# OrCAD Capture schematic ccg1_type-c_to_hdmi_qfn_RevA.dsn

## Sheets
1 PAGE03 : Type-C/Power: size B; title: CCG1 40-QFN Type-C To HDMI Reference Schematic; rev: A
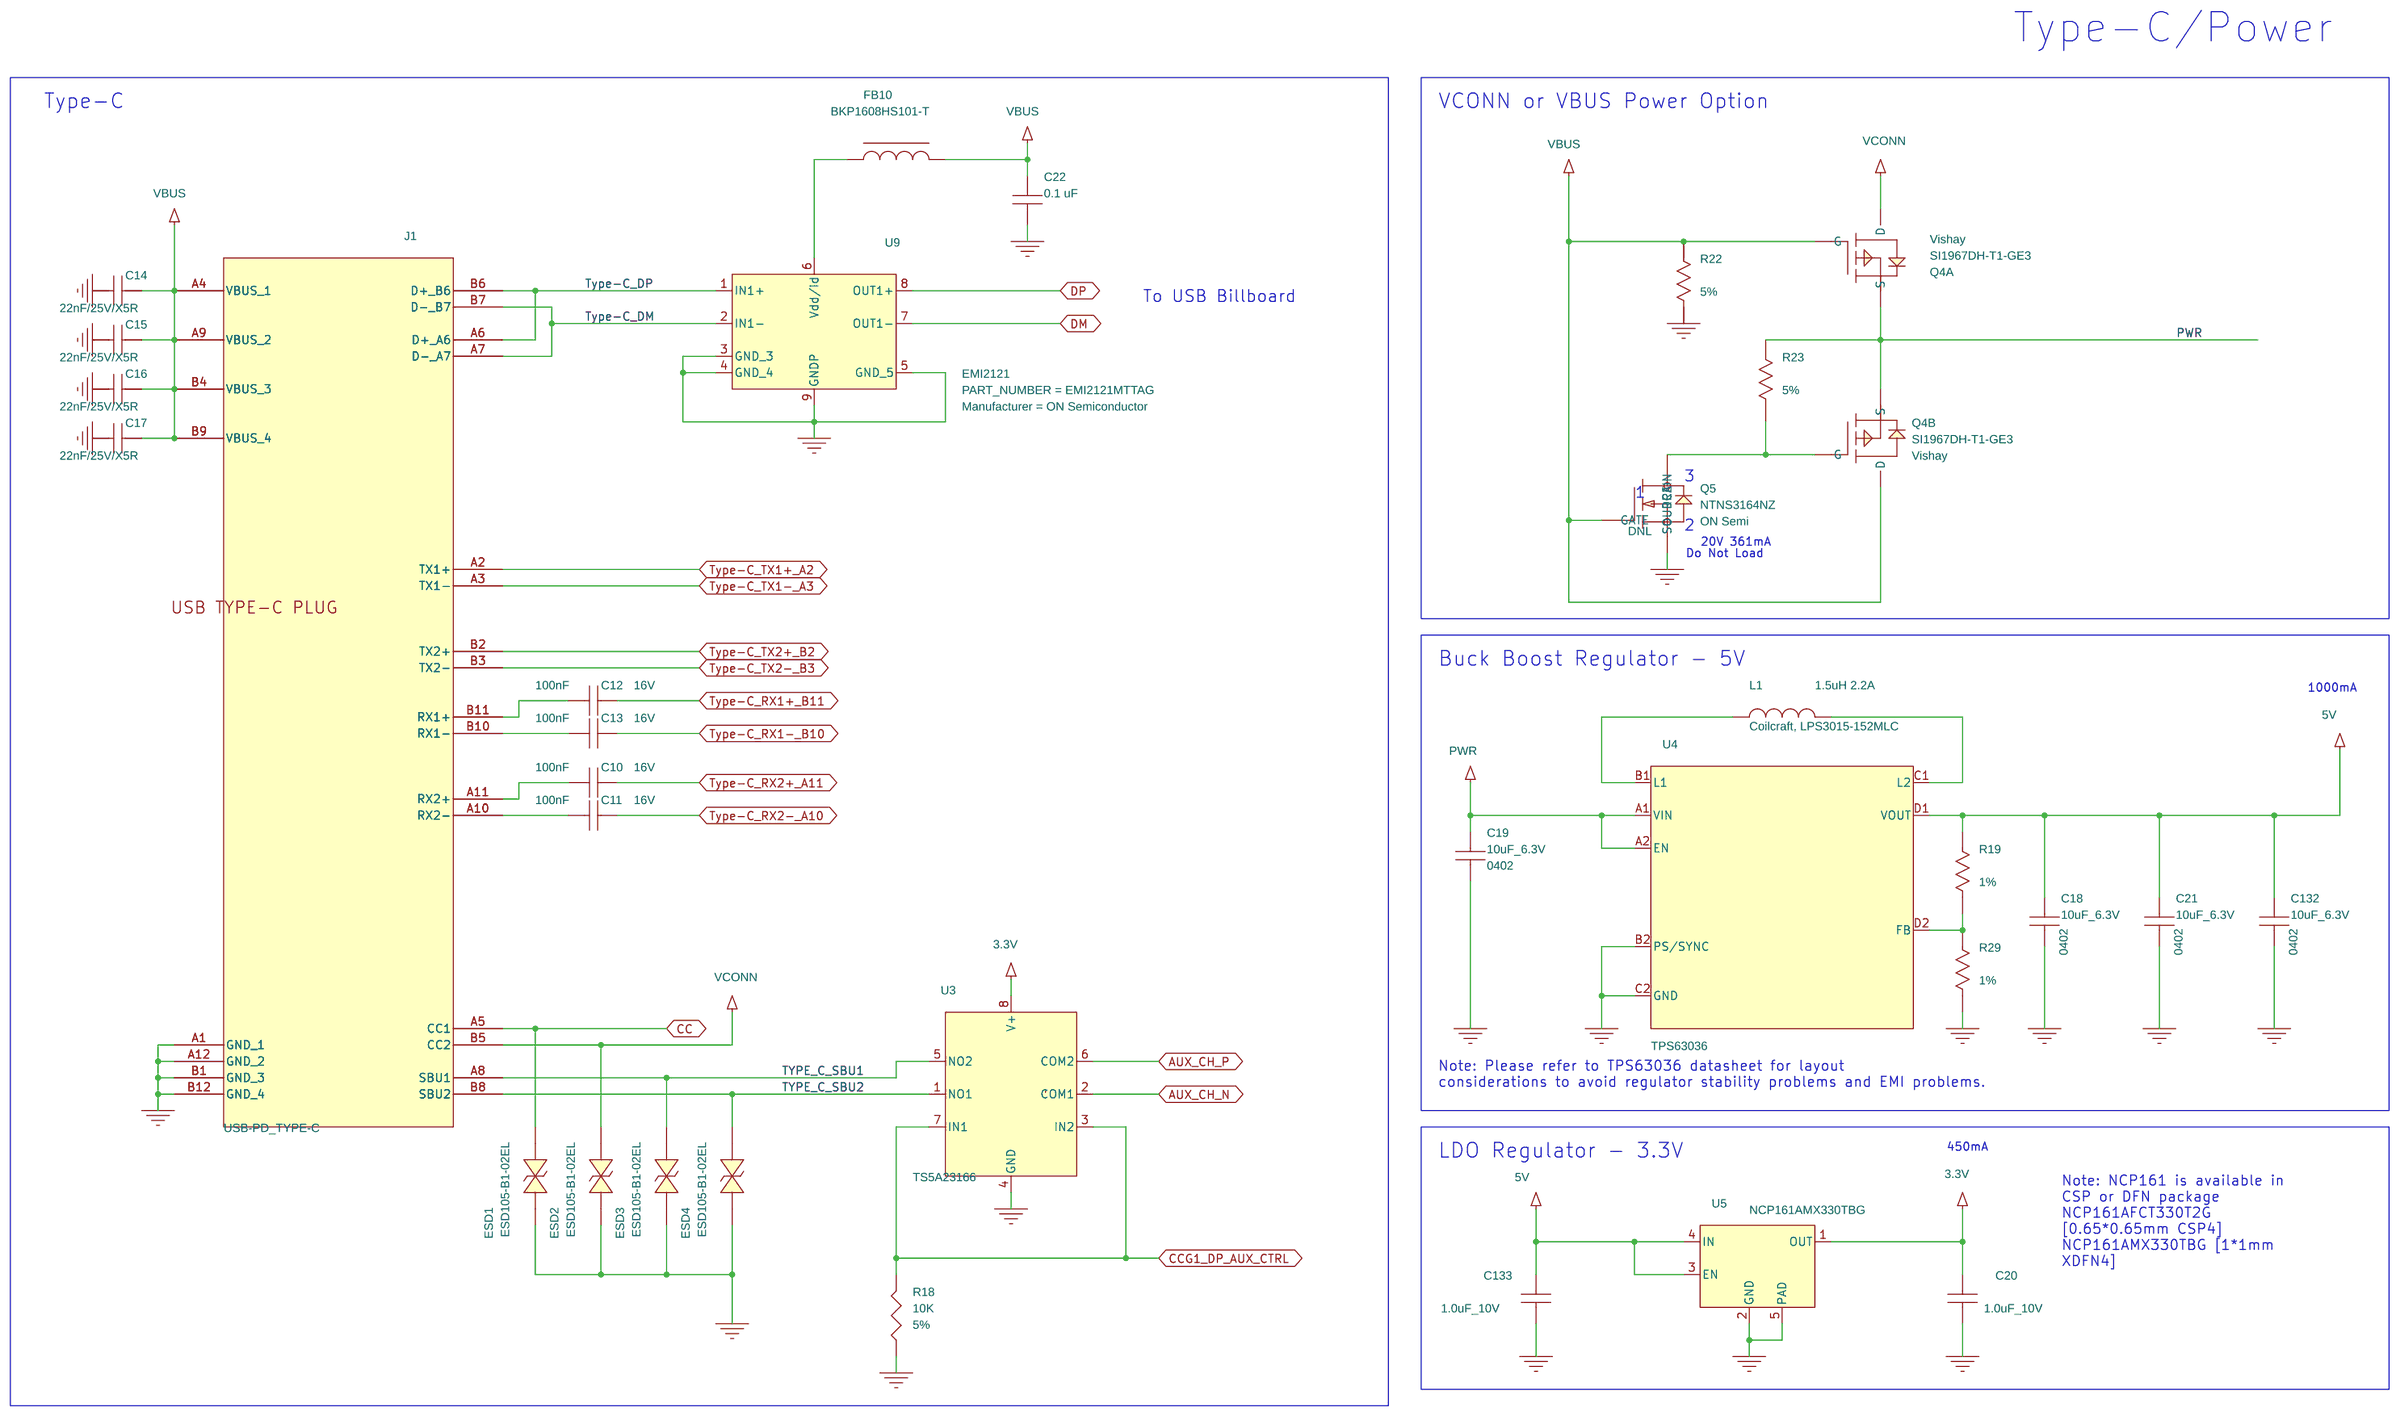
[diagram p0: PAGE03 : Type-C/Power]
2 PAGE01 : Title
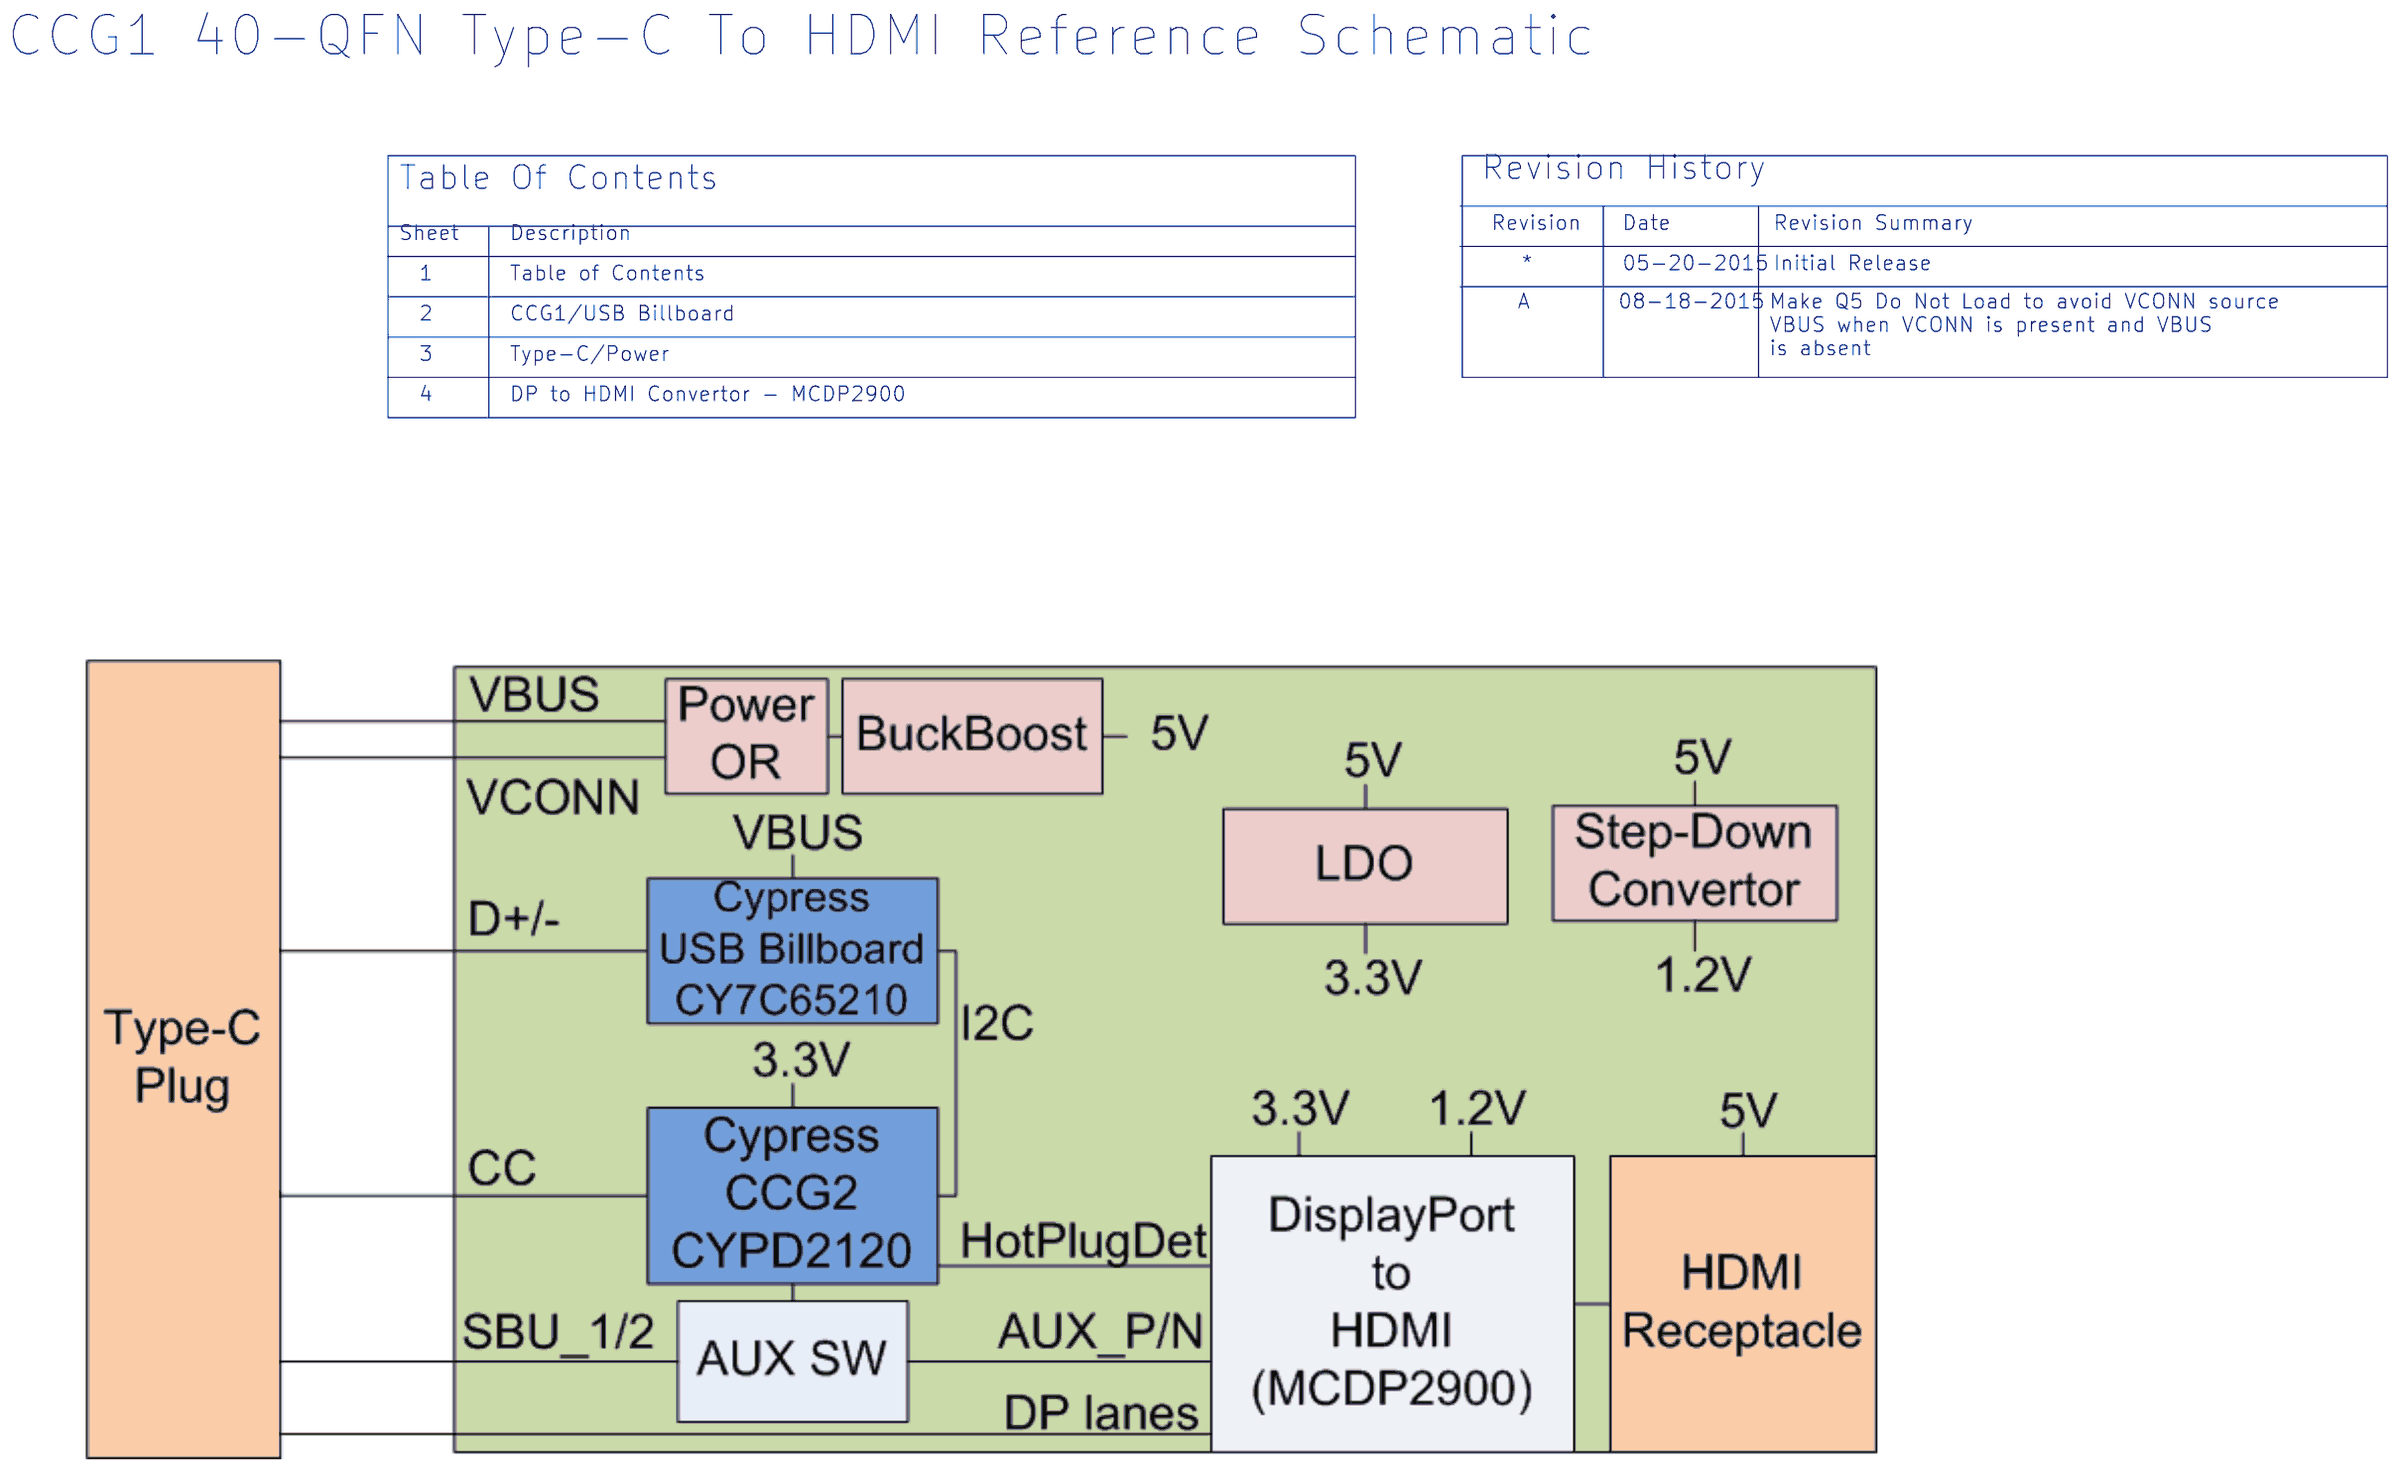
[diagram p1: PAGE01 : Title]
3 PAGE02 : CCG1/USB Billboard: size B
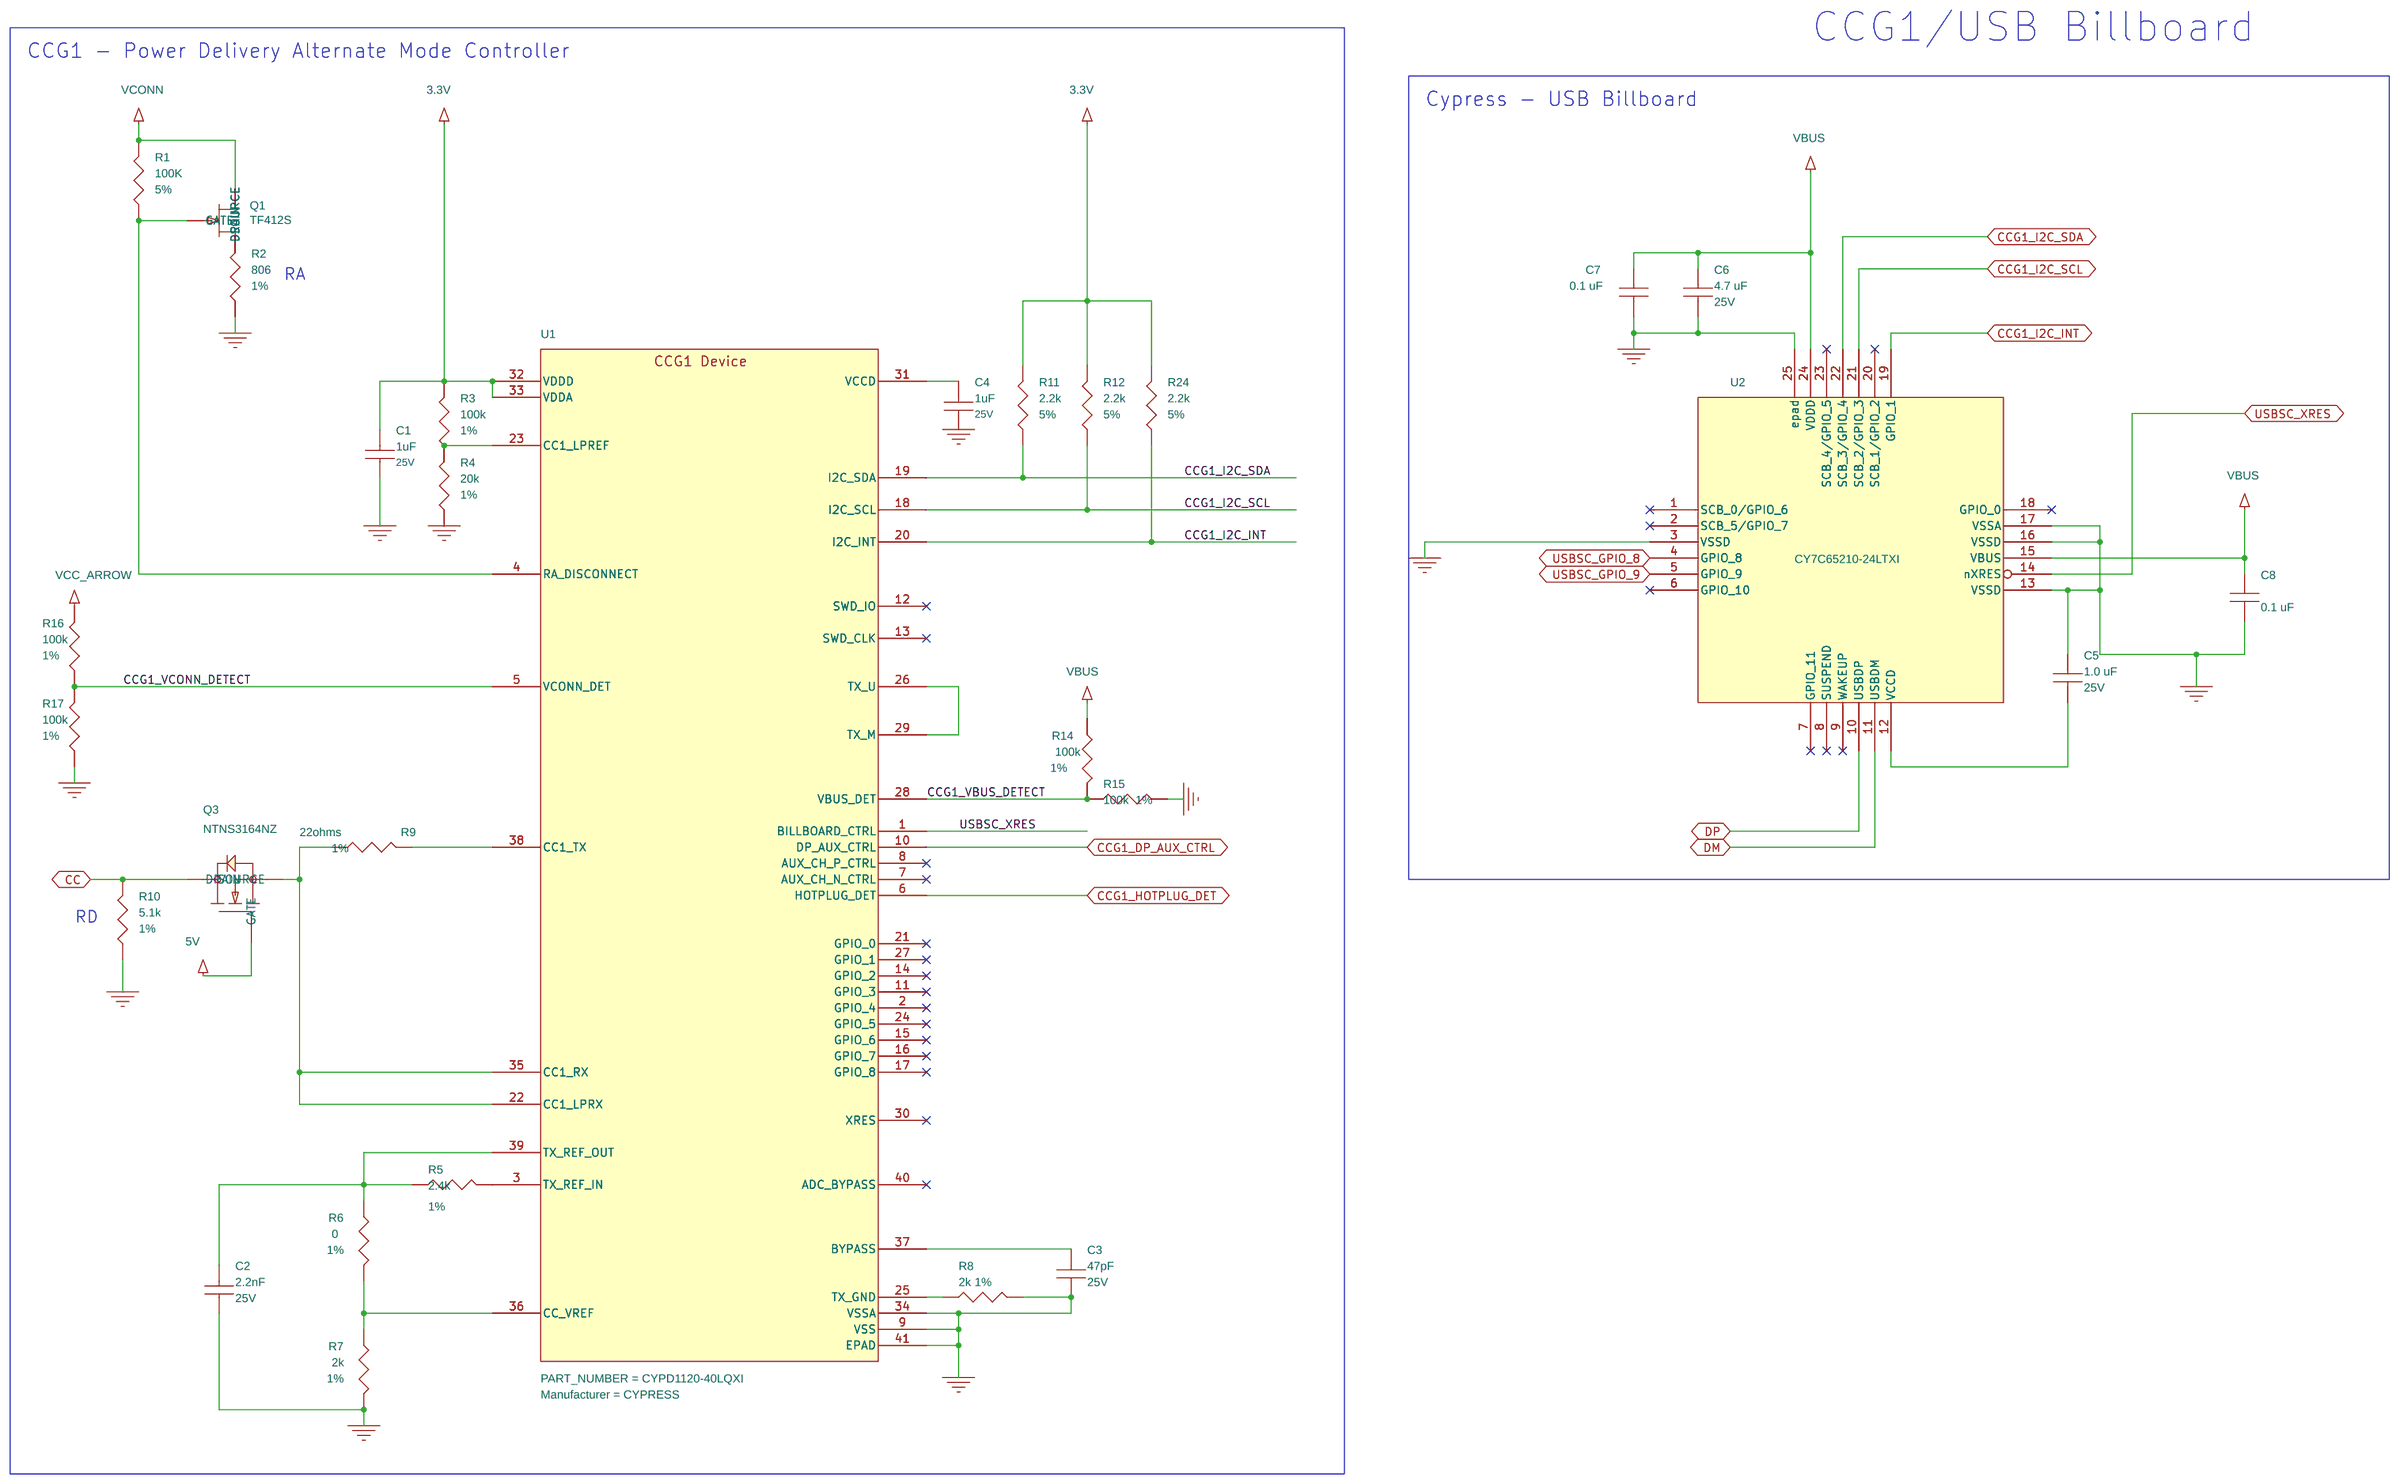
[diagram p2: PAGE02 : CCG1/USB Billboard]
4 PAGE04 : DP to HDMI MCDP2900: size C
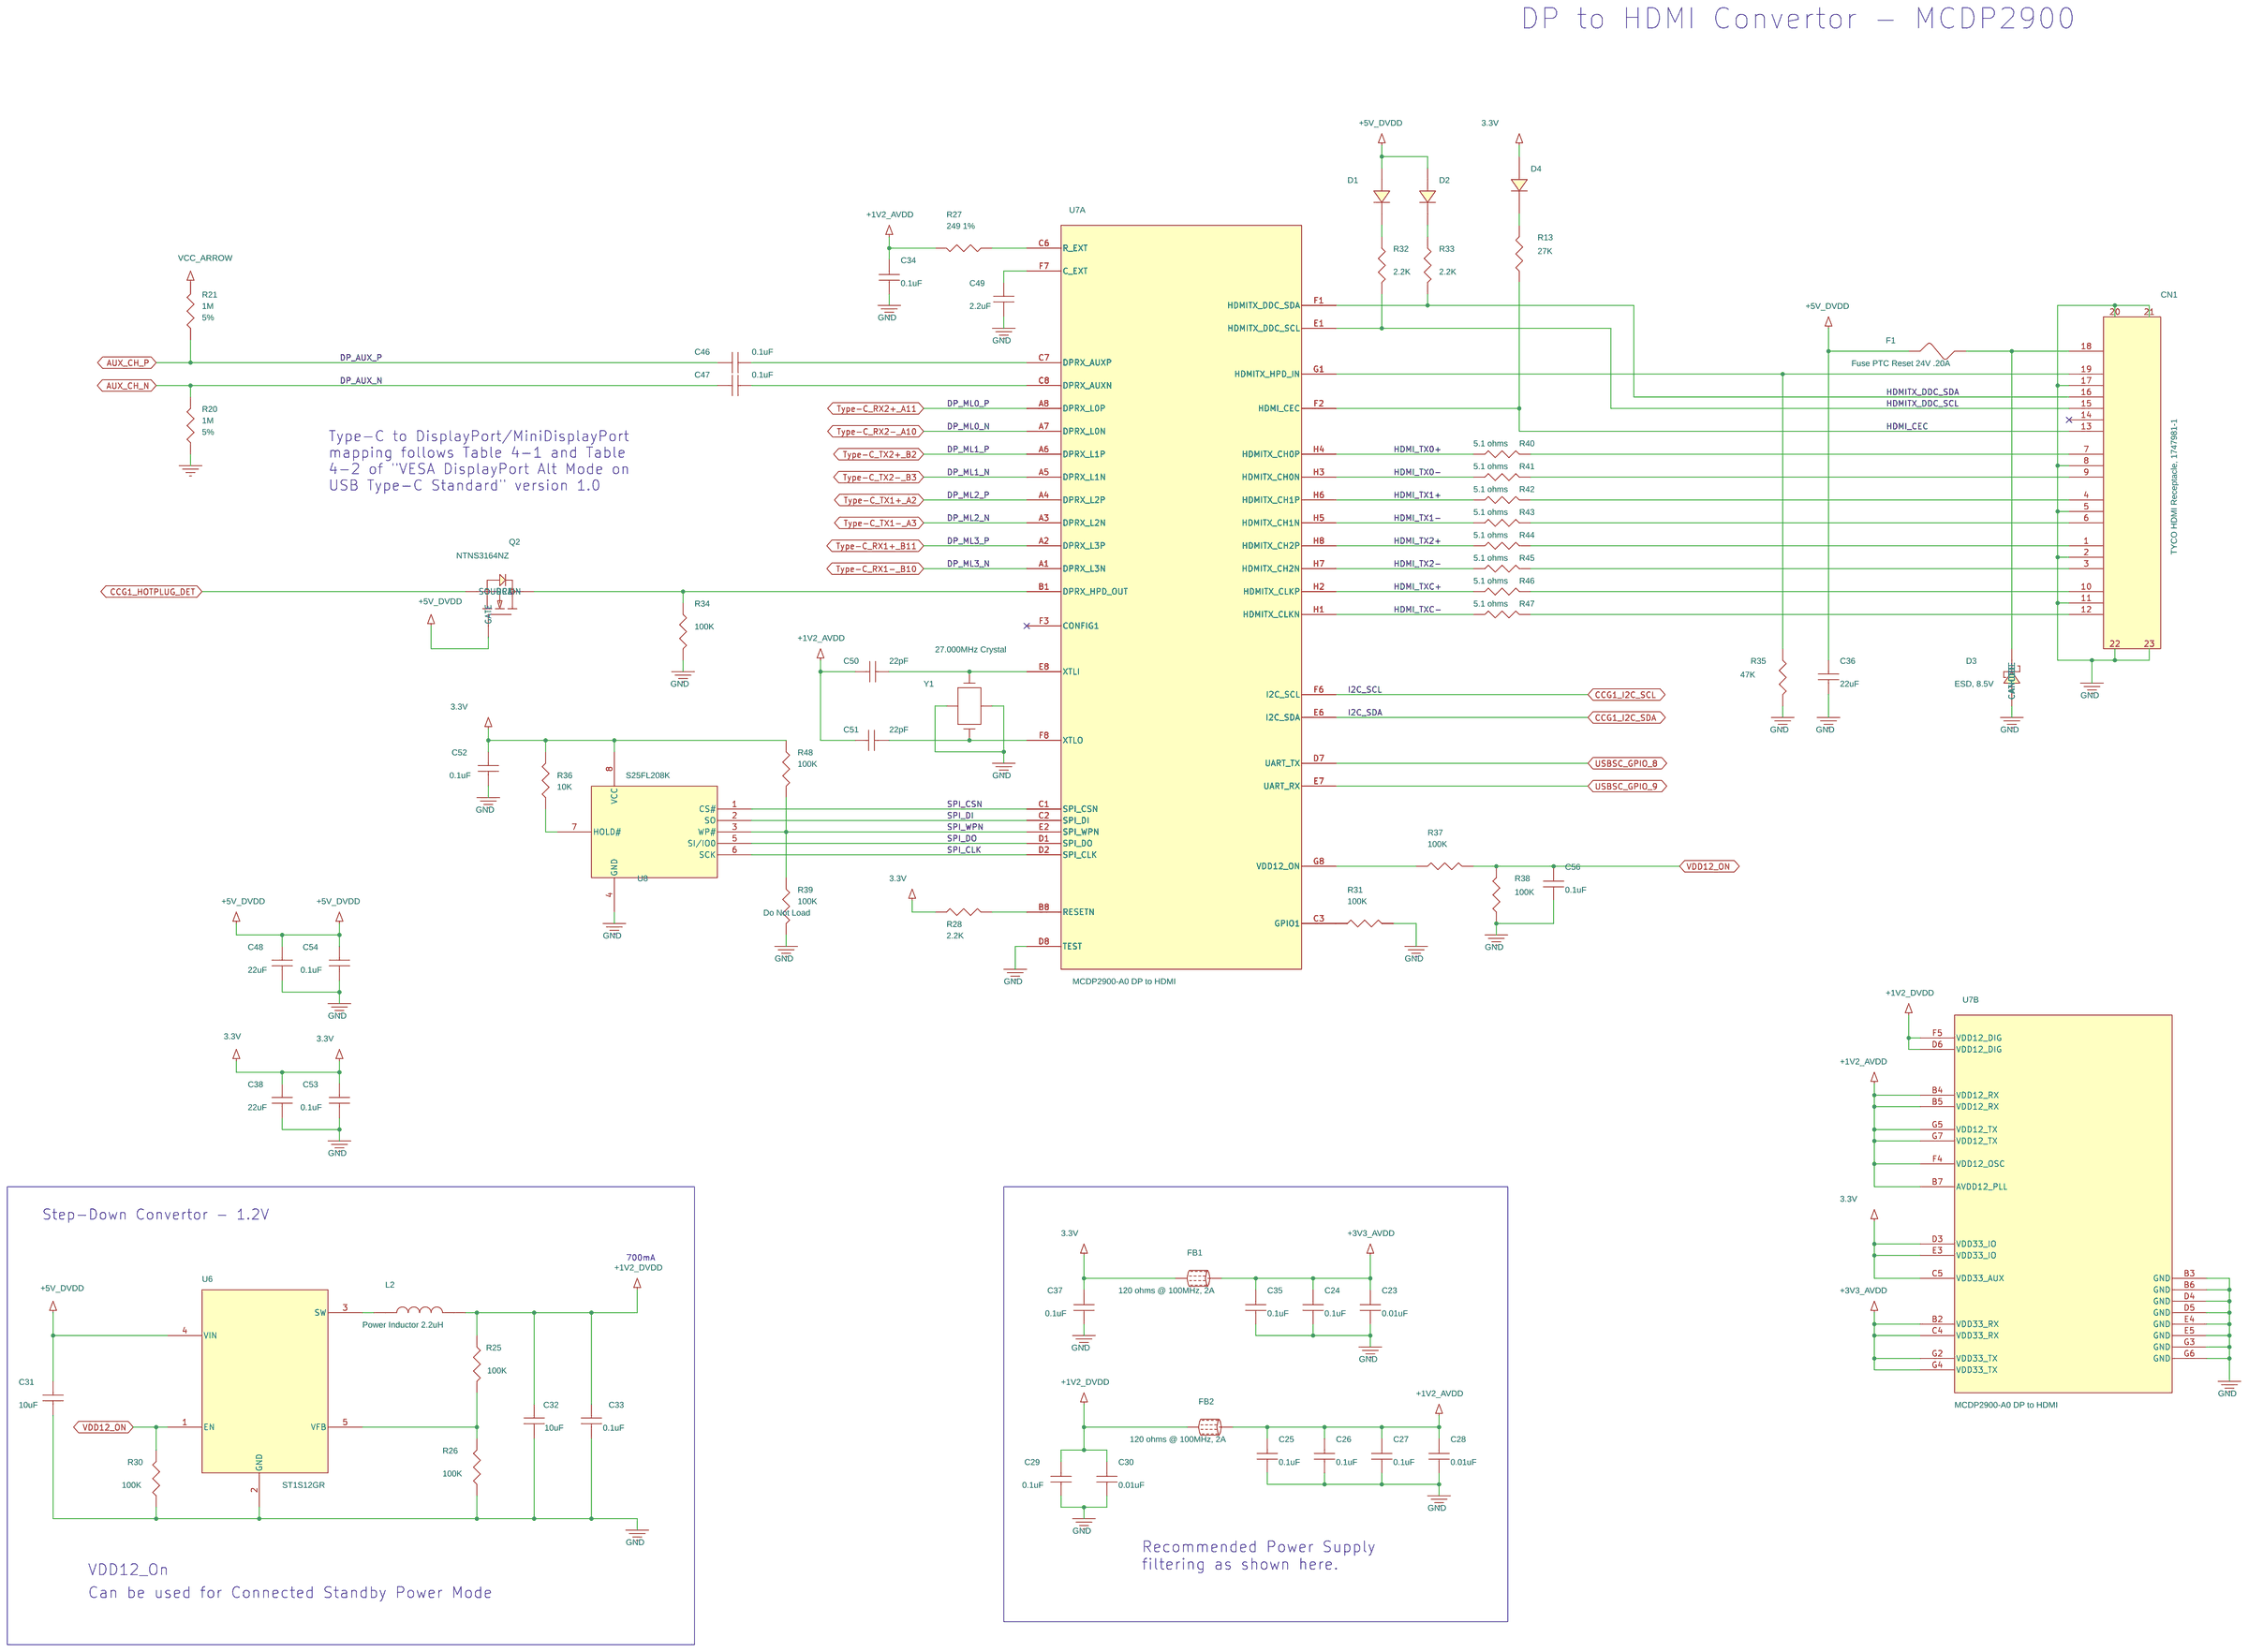
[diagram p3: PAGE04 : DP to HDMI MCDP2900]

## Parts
sheet PAGE02 : CCG1/USB Billboard
C1  1uF  [C0201]
C2  2.2nF  [C0201]
C3  47pF  [C0201]
C4  1uF  [C0201]
C5  1.0 uF  [C0201]
C6  4.7 uF  [C0402]
C7  0.1 uF  [C0201]
C8  0.1 uF  [C0201]
Q1  TF412S  [SOT-883_TF412S]
Q3  NTNS3164NZ  [SOT-883_NTNS3164NZ]
R1  100K  [R0201]
R2  806  [R0201]
R3  100k  [R0201]
R4  20k  [R0201]
R5  2.4k  [R0201]
R6  0  [R0201]
R7  2k  [R0201]
R8  2k  [R0201]
R9  22ohms  [R0201]
R10  5.1k  [R0201]
R11  2.2k  [R0201]
R12  2.2k  [R0201]
R14  100k  [R0201]
R15  100k  [R0201]
R16  100k  [R0201]
R17  100k  [R0201]
R24  2.2k  [R0201]
U1  CCG1_DEVICE  [CYPD1120_40LQXI]
U2  CY7C65210-24LTXI  [24qfn-edited-16]
sheet PAGE03 : Type-C/Power
C10  100nF  [C0201]
C11  100nF  [C0201]
C12  100nF  [C0201]
C13  100nF  [C0201]
C14  22nF/25V/X5R  [C0201]
C15  22nF/25V/X5R  [C0201]
C16  22nF/25V/X5R  [C0201]
C17  22nF/25V/X5R  [C0201]
C18  10uF_6.3V  [0402]
C19  10uF_6.3V  [0402]
C20  1.0uF_10V  [0603]
C21  10uF_6.3V  [0402]
C22  0.1 uF  [C0201]
C132  10uF_6.3V  [0402]
C133  1.0uF_10V  [0603]
ESD1  ESD105-B1-02EL  [TSSLP2-4]
ESD2  ESD105-B1-02EL  [TSSLP2-4]
ESD3  ESD105-B1-02EL  [TSSLP2-4]
ESD4  ESD105-B1-02EL  [TSSLP2-4]
FB10  BKP1608HS101-T  [FB0603]
J1  USB-PD_TYPE-C  [USB-PD_TYPE-C]
L1  1.5uH 2.2A  [74438324010]
Q4  P-MOSFET  [SI1967DH_6SC70]  (sections A,B)
Q5  NTNS3164NZ  [SOT-883_NTNS3164NZ]
R18  10K  [R0201]
R19  470k  [R0402]
R22  100k  [R0201]
R23  100k  [R0201]
R29  51.1k  [R0402]
U3  TS5A23166  [TS5A23166_US8]
U4  TPS63036  [WCSP8]
U5  NCP161AMX330TBG  [XDFN4]
U9  EMI2121  [WDFN8_EMI21]
sheet PAGE04 : DP to HDMI MCDP2900
C23  0.01uF  [C0402]
C24  0.1uF  [C0402]
C25  0.1uF  [C0402]
C26  0.1uF  [C0402]
C27  0.1uF  [C0402]
C28  0.01uF  [C0402]
C29  0.1uF  [C0402]
C30  0.01uF  [C0402]
C31  10uF  [C0805]
C32  10uF  [C0805]
C33  0.1uF  [C0402]
C34  0.1uF  [C0402]
C35  0.1uF  [C0402]
C36  22uF  [C0805]
C37  0.1uF  [C0402]
C38  22uF  [C0805]
C46  0.1uF  [C0402]
C47  0.1uF  [C0402]
C48  22uF  [C0805]
C49  2.2uF  [C0603]
C50  22pF  [C0402]
C51  22pF  [C0402]
C52  0.1uF  [C0402]
C53  0.1uF  [C0402]
C54  0.1uF  [C0402]
C56  0.1uF  [C0402]
CN1  TYCO HDMI Receptacle, 1747981-1  [17479811_HDMI]
D1  Schottky Diode  [ST_SOD523]
D2  Schottky Diode  [ST_SOD523]
D3  ESD, 8.5V  [ST_ST0201]
D4  Schottky Diode  [ST_SOD523]
F1  Fuse PTC Reset 24V .20A  [LITTLEFUSE_1206]
FB1  120 ohms @ 100MHz, 2A  [FB0603]
FB2  120 ohms @ 100MHz, 2A  [FB0603]
L2  Power Inductor 2.2uH  [TDK_VLF3010A]
Q2  NTNS3164NZ  [SOT-883_NTNS3164NZ]
R13  27K  [R0402]
R20  1M  [R0201]
R21  1M  [R0201]
R25  100K  [R0402]
R26  100K  [R0402]
R27  249 1%  [R0402]
R28  2.2K  [R0402]
R30  100K  [R0402]
R31  100K  [R0402]
R32  2.2K  [R0402]
R33  2.2K  [R0402]
R34  100K  [R0402]
R35  47K  [R0402]
R36  10K  [R0402]
R37  100K  [R0402]
R38  100K  [R0402]
R39  100K  [R0402]
R40  5.1 ohms  [R0402]
R41  5.1 ohms  [R0402]
R42  5.1 ohms  [R0402]
R43  5.1 ohms  [R0402]
R44  5.1 ohms  [R0402]
R45  5.1 ohms  [R0402]
R46  5.1 ohms  [R0402]
R47  5.1 ohms  [R0402]
R48  100K  [R0402]
U6  ST1S12GR  [ST_SOT23_5L]
U7  MCDP2900-A0 DP to HDMI  [LFBGA64_7X7MM]  (sections A,B)
U8  S25FL208K  [soic8]
Y1  27.000MHz Crystal  [ECS_4SMD]

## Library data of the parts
C1 C4 = CAP-NP_0: CAP CER 1UF 10V 20% X5R 0201; AC_Voltage: 5V; Manufacturer: Samsung; PART_NUMBER: CL03A105MP3NSNC; RATED_VOLTAGE: 25V; Temp_Coefficient: 0201; Tolerance: 10%
C2 = CAP-NP_0: CAP CER 2200PF 25V 10% X7R 0201; AC_Voltage: 5V; Manufacturer: TDK; PART_NUMBER: C0603X5R1E222K030BA; RATED_VOLTAGE: 25V; Tolerance: 10%
C3 = CAP-NP_0: CAP CER 47PF 25V 10% C0G 0201; AC_Voltage: 5V; Manufacturer: TDK; PART_NUMBER: C0603C0G1E470K030BA; RATED_VOLTAGE: 25V; Tolerance: 10%
C5 = 1_0.0_uFd_0603_X5R_25V_10%: CAP CER 1UF 10V 20% X5R 0201; Manufacturer: Samsung; PART_NUMBER: CL03A105MP3NSNC; VOLTAGE: 25V
C6 = 1_0.0_uFd_0603_X5R_25V_10%: CAP CER 4.7UF 10V 10% X5R 0402; Manufacturer: TDK; PART_NUMBER: C1005X5R1A475K050BC; VOLTAGE: 25V
C7 C22 = 0_0.1_uFd_0402: CAP CER 0.1UF 25V 10% X5R 0201; Manufacturer: TDK; PART_NUMBER: C0603X5R1E104K030BB
C8 = 0_0.1_uFd_0402: CAP CER 0.1UF 25V 10% X5R 0201; BOM_IG: <BOM_IG>; Manufacturer: TDK; PART_NUMBER: C0603X5R1E104K030BB
Q1 = TF412ST5G: JFET N-CH 30V SOT-883 XDFN3; Manufacturer: ON Semi
Q2 Q3 = IRFF220_0: MOSFET N-CH 20V 245MA SOT883; Manufacturer: On Semiconductor; PART_NUMBER: NTNS3164NZT5G
R1 = R: RES SMD 100K OHM 0.5% 1/20W 0201; Manufacturer: Panasonic; PART_NUMBER: ERJ-1RHD1003C; RATING: 1/10W; TOL: 1%; Tolerance: 5%
R2 = R: RES SMD 806 OHM 1% 1/20W 0201; Manufacturer: Panasonic; PART_NUMBER: ERJ-1GEF8060C; RATING: 1/10W; TOL: 1%; Tolerance: 1%
R3 R14-R17 = R: RES SMD 100K OHM 0.5% 1/20W 0201; Manufacturer: Panasonic; PART_NUMBER: ERJ-1RHD1003C; RATING: 1/10W; TOL: 1%; Tolerance: 1%
R4 = R: RES SMD 20K OHM 1% 1/20W 0201; Manufacturer: Panasonic; PART_NUMBER: ERJ-1GEF2002C; RATING: 1/10W; TOL: 1%; Tolerance: 1%
R5 = R: RES SMD 2.4K OHM 1% 1/20W 0201; Manufacturer: Panasonic; PART_NUMBER: ERJ-1GEF2401C; RATING: 1/10W; TOL: 1%; Tolerance: 1%
R6 = R: RES SMD 0.0 OHM JUMPER 1/10W; Manufacturer: Panasonic; PART_NUMBER: ERJ-2GE0R00X; RATING: 1/10W; TOL: 1%; Tolerance: 1%
R7 R8 = R: RES SMD 2K OHM 1% 1/20W 0201; Manufacturer: Panasonic; PART_NUMBER: ERJ-1GEF2001C; RATING: 1/10W; TOL: 1%; Tolerance: 1%
R9 = R: RES 22.0 OHM 1/10W 1% 0201 SMD; Manufacturer: Vishay Dale; PART_NUMBER: CRCW060349R9FKEA; RATING: 1/10W; TOL: 1%; Tolerance: 1%
R10 = R: RES SMD 5.1K OHM 1% 1/20W 0201; Manufacturer: Panasonic; PART_NUMBER: ERJ-1GEF5101C; RATING: 1/10W; TOL: 1%; Tolerance: 1%
R11 R12 R24 = R: RES SMD 2.2K OHM 5% 1/20W 0201; Manufacturer: Panasonic; PART_NUMBER: ERJ-1GEJ222C; RATING: 1/10W; TOL: 1%; Tolerance: 5%
U1 = CCG1_DEVICE: BOM_IGNORE: Customer Supplied; Manufacturer: CYPRESS; PART_NUMBER: CYPD1120-40LQXI
U2 = USB_serial_2: BOM_IGNORE: Customer Supplied
C10-C13 = CAP-NP_0: CAP CER 0.1UF 25V 10% X5R 0201; AC_Voltage: 5V; Manufacturer: TDK; PART_NUMBER: C0603X5R1E104K030BB; RATED_VOLTAGE: 16V; Temp_Coefficient: 0201; Tolerance: 10%
C14-C17 = CAP-NP_0: CAP CER 0.022UF 25V 10% X5R 0201; AC_Voltage: 5V; Manufacturer: TDK; PART_NUMBER: C0603X5R1E223K030BB; RATED_VOLTAGE: 50V; Temp_Coefficient: 0201; Tolerance: 10%
C18 C21 C132 = CAPACITOR_NON-POL: CAP CER 10UF 16V 20% X5R 0603; Manufacturer: Murata; Part_Number: GRM188R60J106ME47D; Tolerance: 20%; mfg: GRM188R60J106KME84D, Murata
C19 = CAPACITOR_NON-POL: CAP CER 10UF 16V 20% X5R 0603; Manufacturer: Murata; Part_Number: GRM188R60J106ME47D; mfg: GRM188R60J106KME84D, Murata
C20 C133 = CAPACITOR_NON-POL: Part_Number: GRM188F51A475ZE20D; Tolerance: -20%, +80%; Voltage: 10V
ESD1-ESD4 = PGB1010603MR: TVS DIODE 5.5VWM 14VC TSLP2-2; Manufacturer: Infineon; Mfg: Infineon; Mfg Part#: ESD105B102ELE6327XTMA1; Mfg Part#(Alt): ESD105B102ELE6327XTMA1; Mfg(Alt): Infineon; PART_NUMBER: ESD105B102ELE6327XTMA1; Package: 0201; RoHS Compliant?: YES; System Name: CS; System_Name: CS
FB10 = Ferrite_Bead: FERRITE CHIP 1.7A 100 OHM 0603; Manufacturer: TAIYO YUDEN; Mfr: TAIYO YUDEN
J1 = USB-PD_TYPE-C_6: BOM_IGNORE: Customer Supplied
L1 = INDUCTOR: INDUCTOR 1.5uH; Lead Free: YES; Manufacturer: Wurth; mfg: Coilcraft, LPS3015-152MLC
Q4 = P-MOSFET_0: MOSFET 2P-CH 20V 1.3A SC70-6; Manufacturer: Vishay; PART_NUMBER: SI1967DH-T1-GE3
Q5 = IRFF220_0: BOM_IG: DNL; Device: Q2; Manufacturer: ON Semi
R18 = R: RES SMD 10K OHM 1% 1/20W 0201; Manufacturer: Panasonic; PART_NUMBER: ERJ-1GEF1002C; RATING: 1/10W; TOL: 5%; Tolerance: 5%
R19 = RESISTOR: RES SMD 287K OHM 1% 1/10W 0402; Manufacturer: Panasonic; PART_NUMBER: ERJ-2RKF2873X; Tolerance: 1%
R22 R23 = RESISTOR: RES SMD 100K OHM 5% 1/20W 0201; BOM_IG: <BOM_IG>; Manufacturer: Panasonic; PART_NUMBER: ERJ-1GEJ104C; Tolerance: 5%
R29 = RESISTOR: RES SMD 51.1K OHM 1% 1/10W 0402; Manufacturer: Panasonic; PART_NUMBER: ERJ-2RKF5112X; Tolerance: 1%
U3 = TS5A23166: IC SWITCH DUAL SPST US8; Manufacturer: Texas Instruments; PART_NUMBER: TS5A23166DCUR
U4 = AOZ1050PI_4: IC REG BUCK BST SYNC ADJ 8WCSP; Manufacturer: Texas Instruments; PART_NUMBER: TPS63036YFGR
U5 = NCP161
U9 = EMI2121: CM-FILTER, ESD PROTECTED, WDFN8; Manufacturer: ON Semiconductor; PART_NUMBER: EMI2121MTTAG
C23 C30 = CAP_NP: CAP CER 0.01uF 10V 10% X5R 0402; Manufacturer: Murata; Manufacturer Part Number: C1608X7R1H103J; Manufacturer's Part Number: GRM155R61A103KA01D; PART_NUMBER: GRM155R61A103KA01D; Part Number: CDN-CAP-2086; Part Type: Ceramic
C24 C26 C27 C35 = CAP_NP: CAP CER 0.1UF 10V 10% X7R 0402; Manufacturer: kemet; Manufacturer Part Number: C1608X7R1H103J; Manufacturer's Part Number: C0402C104K8RACTU; PART_NUMBER: C0402C104K8RACTU; Part Number: CDN-CAP-2013; Part Type: Ceramic
C25 C29 C37 = CAP_NP: CAP CER 0.1UF 10V 10% X7R 0402; Manufacturer: kemet; Manufacturer Part Number: C1608X7R1H104K; Manufacturer's Part Number: C0402C104K8RACTU; PART_NUMBER: C0402C104K8RACTU; Part Number: CDN-CAP-2013; Part Type: Ceramic
C28 = CAP_NP: CAP CER 0.01uF 10V 10% X5R 0402; Manufacturer: Murata; Manufacturer Part Number: C1608X7R1H104K; Manufacturer's Part Number: GRM155R61A103KA01D; PART_NUMBER: GRM155R61A103KA01D; Part Number: CDN-CAP-2086; Part Type: Ceramic
C31 C32 = CAP_NP: CAP CER 10uF 10V 10% X7R 0805; Fitted: YES; Manufacturer: TDK; Manufacturer's Part Number: C2012X7R1A106K; PART_NUMBER: C2012X7R1A106K125AC; Package: C1210; Part Number: CDN-CAP-2065; Part Type: CAP; Voltage_Rating: 16 V
C33 C34 C52-C54 C56 = CAP_NP: CAP CER 0.1UF 10V 10% X7R 0402; Manufacturer: kemet; Manufacturer's Part Number: C0402C104K8RACTU; PART_NUMBER: C0402C104K8RACTU; Part Number: CDN-CAP-2013; Part Type: CAP
C36 = CAP_NP: CAP CER 22uF 6.3V 20% X5R 0805; Manufacturer: TDK; Manufacturer's Part Number: C2012X5R0J226M125AC; PART_NUMBER: C2012X5R0J226M125AC; Part Number: CDN-CAP-2130
C38 C48 = CAP_NP: CAP CER 22uF 16V 10% X5R 0805; Manufacturer: TDK; Manufacturer's Part Number: C2012X5R1C226K; PART_NUMBER: C2012X5R1C226K125AC; Part Number: CDN-CAP-2066
C46 C47 = CAP_NP: CAP CER 0.1UF 10V 10% X7R 0402; Manufacturer: kemet; Manufacturer's Part Number: C0402C104K8RACTU; PART_NUMBER: C0402C104K8RACTU; Part Number: CDN-CAP-2013
C49 = CAP_NP: CAP CER 2.2uF 4V 10% X6S 0603; Manufacturer: TDK; Manufacturer's Part Number: C1608X6S0G225K/0.50; PART_NUMBER: CGB3B3X6S0G225K055AB; Part Number: CDN-CAP-2084
C50 C51 = CAP_NP: CAP CER 22PF 50V 1% C0G 0402; Manufacturer: TDK; Manufacturer's Part Number: C1005C0G1H220F; PART_NUMBER: C1005C0G1H220F050BA; Part Number: CDN-CAP-2016
CN1 = HDMI_4: CONN RECPT HDMI SMT R/A W/O FLNG; Manufacturer: TE; Manufacturer's Part Number: 1747981-1; PART_NUMBER: 1747981-1; Package: Right Angle SMT; Part Number: CDN-CON-0518
D1 D2 D4 = DIODE: DIODE SCHOTTKY 100V 200MA SOD523; Manufacturer: STMicroelectronics; Manufacturer's Part Number: BAT41KFILM; PART_NUMBER: BAT41KFILM; Part Number: CDN-DIO-0012
D3 = DIODE-SCHOTTKY-SK32: TVS DIODE 3VWM ST0201; Manufacturer: STMicroelectronics; Manufacturer's Part Number: ESDAVLC8-1BU2; PART_NUMBER: ESDAVLC8-1BU2; Part Number: CDN-ESD-0027
F1 = FUSE: FUSE PTC RESET 24V .20A 1206; Manufacturer: Littlefuse; Manufacturer's Part Number: 1206L020YR; PART_NUMBER: 1206L020YR; Part Number: CDN-FUE-0015
FB1 FB2 = FERRITE_BEAD: 3A 0.04R 30ohms@100MHz; Manufacturer: Marata Electronics; Manufacturer's Part Number: BLM18PG121SN1D; PART_NUMBER: BLM18PG121SN1D; Part Number: CDN-FER-0018
L2 = INDUCTOR_v2: FIXED IND 2.2UH 1A 120 MOHM SMD; Manufacturer: TDK Corp; Manufacturer's Part Number: VLF3010AT-2R2M1R0; PART_NUMBER: VLF3010AT-2R2M1R0; Part Number: CDN-IND-0020
R13 = R: RES SMD 27K OHM 1% 1/10W 0402; Manufacturer: Panasonic - ECG; Manufacturer's Part Number: ERJ-2GEJ302X; PART_NUMBER: ERJ-2RKF2702X; Part Number: CDN-RES-2125; PartNumber: ERJ-3GSYJ470; Tolerance: 0.05
R20 = R: RES SMD 4.7M OHM 5% 1/20W 0201; Manufacturer: Panasonic; PART_NUMBER: ERJ-1GEJ475C; RATING: 1/10W; TOL: 5%; Tolerance: 5%
R21 = R: RES SMD 470K OHM 5% 1/20W 0201; Manufacturer: Panasonic; PART_NUMBER: ERJ-1GEJ474C; RATING: 1/10W; TOL: 1%; Tolerance: 5%
R25 R26 R30 R31 R37 R38 R40-R48 = R: RES 100K OHM 1/10W 1% 0402 SMD; Fitted: YES; Manufacturer: Panasonic - ECG; Manufacturer's Part Number: ERJ-2RKF1003X; PART_NUMBER: ERJ-2RKF1003X; Part Number: CDN-RES-2052; Part Type: RES; Tolerance: 0.01
R27 = R: RES SMD 249 OHM 1% 1/10W 0402; GenesisPartNumber: NA; Manufacturer: Panasonic - ECG; Manufacturer's Part Number: ERJ-2RKF2490X; PART_NUMBER: ERJ-2RKF2490X; Part Number: CDN-RES-2032; Tolerance: 0.01; Value2: 1%
R28 R32 R33 = R: RES 2.2K OHM 1/10W 5% 0402 SMD; Manufacturer: Panasonic - ECG; Manufacturer Part Number: ERJ-3EKF4701V; Manufacturer's Part Number: ERJ-2GEJ222X; PART_NUMBER: ERJ-2GEJ222X; Part Number: CDN-RES-2131; Tolerance: 0.05
R34 = R: RES 100K OHM 1/10W 1% 0402 SMD; Manufacturer: Panasonic - ECG; Manufacturer's Part Number: ERJ-2GEJ105X; PART_NUMBER: ERJ-2RKF1003X; Part Number: CDN-RES-2121; Tolerance: 0.05
R35 = R: RES SMD 47K OHM 1% 1/10W 0402; Fitted: YES; Manufacturer: Panasonic - ECG; Manufacturer's Part Number: ERJ-2RKF1003X; PART_NUMBER: ERJ-2RKF4702X; Part Number: CDN-RES-2052; Part Type: RES; Tolerance: 0.01
R36 = R: RES 10K OHM 1/10W 5% 0402 SMD; Manufacturer: Panasonic - ECG; Manufacturer's Part Number: ERJ-2GEJ103X; PART_NUMBER: ERJ-2GEJ103X; Part Number: CDN-RES-2123; Tolerance: 0.05
R39 = R: RES 100K OHM 1/10W 1% 0402 SMD; BOM_IG: Do Not Load; Fitted: YES; Manufacturer: Panasonic - ECG; Manufacturer's Part Number: ERJ-2RKF1003X; PART_NUMBER: ERJ-2RKF1003X; Part Number: CDN-RES-2052; Part Type: RES; Tolerance: 0.01
U6 = ST1S12GR: IC REG BUCK SYNC ADJ 0.7A TSOT23; Manufacturer: STMicroelectronics; Part Number: CDN-IC-1023
U7 = MCDP2800_1: BOM_IGNORE: CUSTOMER SUPPLIED
U8 = SST25VF020_0: IC FLASH 8MBIT 80MHZ 8SOIC; Manufacturer: Microchip Technology; PART_NUMBER: SST25VF080B-80-4C-S2AE-T
Y1 = CRYSTAL: CRYSTAL 27MHZ 20PF SMD; Manufacturer: ECS Inc; Manufacturer's Part Number: ECS-270-20-33-TR; PART_NUMBER: ECS-270-20-33-TR; Part Number: CDN-OSC-0025

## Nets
+1V2_AVDD: C25.2 C26.2 C27.2 C28.2 C34.2 C50.2 C51.1 FB2.2 R27.2 U7.B4(VDD12_RX) U7.B5(VDD12_RX) U7.B7(AVDD12_PLL) U7.F4(VDD12_OSC) U7.G5(VDD12_TX) U7.G7(VDD12_TX)
+1V2_DVDD: C29.2 C30.2 C32.1 C33.1 FB2.1 L2.2 R25.2 U7.D6(VDD12_DIG) U7.F5(VDD12_DIG)
+3V3_AVDD: C23.2 C24.2 C35.2 FB1.2 U7.B2(VDD33_RX) U7.C4(VDD33_RX) U7.G2(VDD33_TX) U7.G4(VDD33_TX)
+3V3_DVDD: C1.2 C20.1 C37.2 C38.1 C52.1 C53.1 D4.A FB1.1 R3.1 R11.1 R12.1 R21.1 R24.1 R28.1 R36.1 R48.2 U1.32(VDDD) U1.33(VDDA) U3.8(V+) U5.1(OUT) U7.C5(VDD33_AUX) U7.D3(VDD33_IO) U7.E3(VDD33_IO) U8.8(VCC)
+5V_DVDD: C18.1 C21.1 C31.1 C36.1 C48.1 C54.1 C132.1 C133.1 D1.A D2.A F1.2 Q2.1(GATE) Q3.1(GATE) R19.2(B) U4.D1(VOUT) U5.3(EN) U5.4(IN) U6.4(VIN)
GND: C1.1 C2.1 C3.1 C4.1 C5.1 C6.2 C7.2 C8.2 C14.2 C15.2 C16.2 C17.2 C18.2 C19.2 C20.2 C21.2 C22.2 C23.1 C24.1 C25.1 C26.1 C27.1 C28.1 C29.1 C30.1 C31.2 C32.2 C33.2 C34.1 C35.1 C36.2 C37.1 C38.2 C48.2 C49.2 C52.2 C53.2 C54.2 C56.1 C132.2 C133.2 CN1.2 CN1.5 CN1.8 CN1.11 CN1.17 CN1.20(SH) CN1.21(SH) CN1.22(SH) CN1.23(SH) D3.A(ANODE) ESD1.1 ESD2.1 ESD3.1 ESD4.1 J1.A1(GND_1) J1.A12(GND_2) J1.B1(GND_3) J1.B12(GND_4) Q5.2(SOURCE) R2.2 R4.2 R7.2 R8.1 R10.2 R15.2 R17.2 R18.2 R20.2 R22.1(A) R26.1 R29.1(A) R30.1 R31.1 R34.2 R35.2 R38.2 R39.1 U1.9(VSS) U1.34(VSSA) U1.41(EPAD) U2.3(VSSD) U2.13(VSSD) U2.16(VSSD) U2.17(VSSA) U2.25(epad) U3.4(GND) U4.B2(PS/SYNC) U4.C2(GND) U5.2(GND) U5.5(PAD) U6.2(GND) U7.B3(GND) U7.B6(GND) U7.D4(GND) U7.D5(GND) U7.D8(TEST) U7.E4(GND) U7.E5(GND) U7.G3(GND) U7.G6(GND) U8.4(GND) U9.3(GND) U9.4(GND) U9.5(GND) U9.9(GNDP) Y1.2 Y1.4
VBUS: C6.1 C7.1 C8.1 C14.1 C15.1 C16.1 C17.1 C22.1 FB10.2 J1.A4(VBUS_1) J1.A9(VBUS_2) J1.B4(VBUS_3) J1.B9(VBUS_4) Q4.2(G) Q4.3(D) Q5.1(GATE) R14.1 R22.2(B) U2.15(VBUS) U2.24(VDDD)
VDD12_ON: C56.2 R30.2 R37.1 R38.1 U6.1(EN)
AUX_CH_N: C47.2 R20.1 U3.2(COM1)
AUX_CH_P: C46.2 R21.2 U3.6(COM2)
CC: ESD1.2 J1.A5(CC1) Q3.3(DRAIN) R10.1
CCG1_DP_AUX_CTRL: R18.1 U1.10(DP_AUX_CTRL) U3.3(IN2) U3.7(IN1)
CCG1_HOTPLUG_DET: Q2.2(SOURCE) U1.6(HOTPLUG_DET)
CCG1_I2C_INT: R24.2 U1.20(I2C_INT) U2.19(GPIO_1)
CCG1_I2C_SCL: R12.2 U1.18(I2C_SCL) U2.21(SCB_2/GPIO_3) U7.F6(I2C_SCL)
CCG1_I2C_SDA: R11.2 U1.19(I2C_SDA) U2.22(SCB_3/GPIO_4) U7.E6(I2C_SDA)
CCG1_VBUS_DETECT: R14.2 R15.1 U1.28(VBUS_DET)
CCG1_VCONN_DETECT: R16.2 R17.1 U1.5(VCONN_DET)
DM: U2.11(USBDM) U9.7(OUT1-)
DP: U2.10(USBDP) U9.8(OUT1+)
HDMI_CEC: CN1.13 R13.1 U7.F2(HDMI_CEC)
HDMI_TX0+: R40.2 U7.H4(HDMITX_CH0P)
HDMI_TX0-: R41.2 U7.H3(HDMITX_CH0N)
HDMI_TX1+: R42.2 U7.H6(HDMITX_CH1P)
HDMI_TX1-: R43.2 U7.H5(HDMITX_CH1N)
HDMI_TX2+: R44.2 U7.H8(HDMITX_CH2P)
HDMI_TX2-: R45.2 U7.H7(HDMITX_CH2N)
HDMI_TXC+: R46.2 U7.H2(HDMITX_CLKP)
HDMI_TXC-: R47.2 U7.H1(HDMITX_CLKN)
HDMITX_DDC_SCL: CN1.15 R32.2 U7.E1(HDMITX_DDC_SCL)
HDMITX_DDC_SDA: CN1.16 R33.2 U7.F1(HDMITX_DDC_SDA)
PWR: C19.1 Q4.1(S) Q4.4(S) R23.2(B) U4.A1(VIN) U4.A2(EN)
SPI_CLK: U7.D2(SPI_CLK) U8.6(SCK)
SPI_CSN: U7.C1(SPI_CSN) U8.1(CS#)
SPI_DI: U7.C2(SPI_DI) U8.2(SO)
SPI_DO: U7.D1(SPI_DO) U8.5(SI/IO0)
SPI_WPN: R39.2 R48.1 U7.E2(SPI_WPN) U8.3(WP#)
Type-C_DM: J1.A7(D-) J1.B7(D-) U9.2(IN1-)
Type-C_DP: J1.A6(D+) J1.B6(D+) U9.1(IN1+)
Type-C_RX1+_B11: C12.1 U7.A2(DPRX_L3P)
Type-C_RX1-_B10: C13.1 U7.A1(DPRX_L3N)
Type-C_RX2+_A11: C10.1 U7.A8(DPRX_L0P)
Type-C_RX2-_A10: C11.1 U7.A7(DPRX_L0N)
Type-C_TX1+_A2: J1.A2(TX1+) U7.A4(DPRX_L2P)
Type-C_TX1-_A3: J1.A3(TX1-) U7.A3(DPRX_L2N)
Type-C_TX2+_B2: J1.B2(TX2+) U7.A6(DPRX_L1P)
Type-C_TX2-_B3: J1.B3(TX2-) U7.A5(DPRX_L1N)
TYPE_C_SBU1: ESD3.2 J1.A8(SBU1) U3.5(NO2)
TYPE_C_SBU2: ESD4.2 J1.B8(SBU2) U3.1(NO1)
USBSC_GPIO_8: U2.4(GPIO_8) U7.D7(UART_TX)
USBSC_GPIO_9: U2.5(GPIO_9) U7.E7(UART_RX)
USBSC_XRES: U1.1(BILLBOARD_CTRL) U2.14(nXRES)
VCONN: ESD2.2 J1.B5(CC2) Q1.2(DRAIN) Q4.6(D) R1.1 R16.1
N17331009: C4.2 U1.31(VCCD)
N17331047: Q3.2(SOURCE) R9.2 U1.22(CC1_LPRX) U1.35(CC1_RX)
N17331135: C2.2 R5.1 R6.1 U1.39(TX_REF_OUT)
N17331165: Q1.3(GATE) R1.2 U1.4(RA_DISCONNECT)
N17331171: Q1.1(SOURCE) R2.1
N17331216: R9.1 U1.38(CC1_TX)
N17331307: R6.2 R7.1 U1.36(CC_VREF)
N17331335: U1.26(TX_U) U1.29(TX_M)
N17331341: C3.2 U1.37(BYPASS)
N17331343: R8.2 U1.25(TX_GND)
N17331355: R3.2 R4.1 U1.23(CC1_LPREF)
N17335610: C10.2 J1.A11(RX2+)
N17335735: C12.2 J1.B11(RX1+)
N17335816: C13.2 J1.B10(RX1-)
N17335856: C11.2 J1.A10(RX2-)
N17341095: C5.2 U2.12(VCCD)
N17391134: FB10.1 U9.6(Vdd/Id)
N17415742: Q4.5(G) Q5.3(DRAIN) R23.1(A)
N17431531: R25.1 R26.2 U6.5(VFB)
N17431641: R27.1 U7.C6(R_EXT)
N17431780: CN1.18 D3.C(CATHODE) F1.1
N17431926: R37.2 U7.G8(VDD12_ON)
N17432029: R36.2 U8.7(HOLD#)
N17432110: CN1.19 R35.1 U7.G1(HDMITX_HPD_IN)
N17432319: Q2.3(DRAIN) R34.1 U7.B1(DPRX_HPD_OUT)
N17432474: C46.1 U7.C7(DPRX_AUXP)
N17432476: C47.1 U7.C8(DPRX_AUXN)
N17432557: R28.2 U7.B8(RESETN)
N17432605: C49.1 U7.F7(C_EXT)
N17432654: C50.1 U7.E8(XTLI) Y1.3
N17432656: C51.2 U7.F8(XTLO) Y1.1
N17433369: L1.2 U4.C1(L2)
N17433371: L1.1 U4.B1(L1)
N17433513: R19.1(A) R29.2(B) U4.D2(FB)
N17452613: L2.1 U6.3(SW)
N17492814: D4.C R13.2
N17492905: D2.C R33.1
N17492906: D1.C R32.1
N17512007: R5.2 U1.3(TX_REF_IN)
N17514760: CN1.7 R40.1
N17514806: CN1.9 R41.1
N17514826: CN1.4 R42.1
N17514846: CN1.6 R43.1
N17514866: CN1.1 R44.1
N17514886: CN1.3 R45.1
N17514906: CN1.10 R46.1
N17514926: CN1.12 R47.1
N17526210: R31.2 U7.C3(GPIO1)

Not connected (* = marked no-connect by the designer): CN1 14*; U1 2(GPIO_4)* 7(AUX_CH_N_CTRL)* 8(AUX_CH_P_CTRL)* 11(GPIO_3)* 12(SWD_IO)* 13(SWD_CLK)* 14(GPIO_2)* 15(GPIO_6)* 16(GPIO_7)* 17(GPIO_8)* 21(GPIO_0)* 24(GPIO_5)* 27(GPIO_1)* 30(XRES)* 40(ADC_BYPASS)*; U2 1(SCB_0/GPIO_6)* 2(SCB_5/GPIO_7)* 6(GPIO_10)* 7(GPIO_11)* 8(SUSPEND)* 9(WAKEUP)* 18(GPIO_0)* 20(SCB_1/GPIO_2)* 23(SCB_4/GPIO_5)*; U7 F3(CONFIG1)*

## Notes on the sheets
sheet 1
- Type-C/Power
- Type-C
- VCONN or VBUS Power Option
- To USB Billboard
- 3
- 1
- 2
- 20V 361mA
- Do Not Load
- Buck Boost Regulator - 5V
- 1000mA
- Note: Please refer to TPS63036 datasheet for layout
  considerations to avoid regulator stability problems and EMI problems.
- LDO Regulator - 3.3V
- 450mA
- Note: NCP161 is available in
  CSP or DFN package
  NCP161AFCT330T2G
  [0.65*0.65mm CSP4]
  NCP161AMX330TBG [1*1mm
  XDFN4]
sheet 2
- CCG1 40-QFN Type-C To HDMI Reference Schematic
- Table Of Contents
- Revision History
- Sheet
- Description
- Revision
- Date
- Revision Summary
- *
- 05-20-2015
- Initial Release
- 1
- Table of Contents
- 2
- CCG1/USB Billboard
- A
- 08-18-2015
- Make Q5 Do Not Load to avoid VCONN source
  VBUS when VCONN is present and VBUS
  is absent
- 3
- Type-C/Power
- 4
- DP to HDMI Convertor - MCDP2900
sheet 3
- CCG1/USB Billboard
- CCG1 - Power Delivery Alternate Mode Controller
- Cypress - USB Billboard
- RA
- RD
sheet 4
- DP to HDMI Convertor - MCDP2900
- Type-C to DisplayPort/MiniDisplayPort
  mapping follows Table 4-1 and Table
  4-2 of "VESA DisplayPort Alt Mode on
  USB Type-C Standard" version 1.0
- Step-Down Convertor - 1.2V
- 700mA
- Recommended Power Supply
  filtering as shown here.
- VDD12_On
- Can be used for Connected Standby Power Mode
